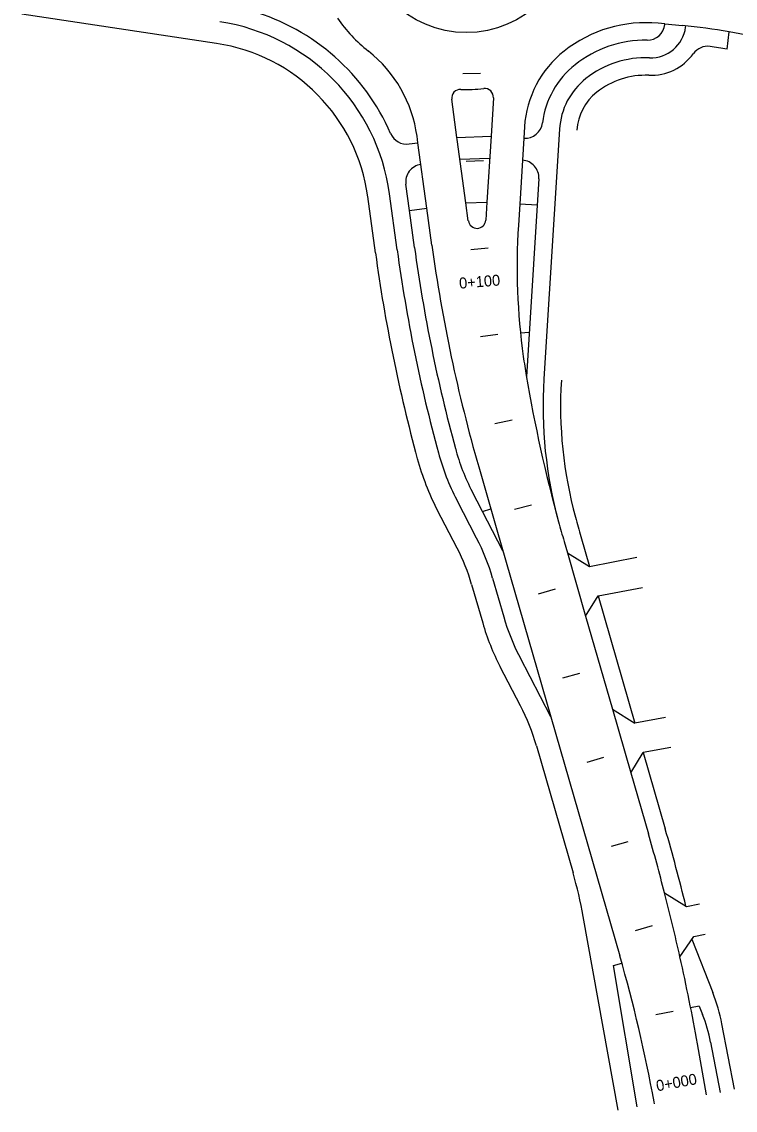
# Model space of a CAD drawing. Extents: x 6503541 to 6503743, y 5888004 to 5888145.
# Drawn here: x 6503692.725 to 6503694.679, y 5888109.241 to 5888112.224 of the extents above; entities that cross this region are included whole.
import ezdxf

# ---------------------------------------------------------------- set-up
doc = ezdxf.new("R2010")
doc.units = 0
doc.layers.add('12', color=7, linetype='Continuous')

msp = doc.modelspace()

# ---------------------------------------------------------------- linework, layer by layer
at = {"layer": '12'}
for p, q in [((6503693.2577, 5888112.1644), (6503692.7245, 5888112.2444)), ((6503694.4861, 5888112.2178), (6503694.4681, 5888112.2196)), ((6503694.4859, 5888112.2166), (6503694.4861, 5888112.2178)), ((6503694.4861, 5888112.2178), (6503694.5342, 5888112.2132)), ((6503694.5428, 5888112.2092), (6503694.5432, 5888112.2124)), ((6503694.6563, 5888112.1489), (6503694.6621, 5888112.196)), ((6503693.9165, 5888111.9068), (6503693.9023, 5888112.0112)), ((6503694.0164, 5888112.0154), (6503694.0098, 5888111.9102)), ((6503694.1016, 5888111.9356), (6503694.0996, 5888111.9046)), ((6503694.1974, 5888111.9296), (6503694.1546, 5888111.2447)), ((6503693.7854, 5888111.8889), (6503693.8095, 5888111.8922)), ((6503693.8095, 5888111.8922), (6503693.8071, 5888111.91)), ((6503693.834, 5888111.7129), (6503693.8095, 5888111.8922)), ((6503693.9165, 5888111.9068), (6503694.0098, 5888111.9102)), ((6503693.9173, 5888111.9008), (6503693.9165, 5888111.9068)), ((6503693.941, 5888111.7275), (6503693.9173, 5888111.9008)), ((6503694.0098, 5888111.9102), (6503693.9985, 5888111.7296)), ((6503694.0996, 5888111.9046), (6503694.0884, 5888111.724)), ((6503694.1001, 5888111.9045), (6503694.0996, 5888111.9046)), ((6503693.9247, 5888111.847), (6503694.0061, 5888111.85)), ((6503694.1408, 5888111.7935), (6503694.1363, 5888111.721)), ((6503693.7864, 5888111.7064), (6503693.7766, 5888111.7784)), ((6503693.6933, 5888111.5903), (6503693.6723, 5888111.7444)), ((6503693.7527, 5888111.5984), (6503693.7317, 5888111.7525)), ((6503693.7864, 5888111.7064), (6503693.834, 5888111.7129)), ((6503693.8003, 5888111.6049), (6503693.7864, 5888111.7064)), ((6503693.8478, 5888111.6114), (6503693.834, 5888111.7129)), ((6503693.941, 5888111.7275), (6503693.9985, 5888111.7296)), ((6503693.9477, 5888111.6783), (6503693.941, 5888111.7275)), ((6503693.9985, 5888111.7296), (6503693.9955, 5888111.6801)), ((6503694.0884, 5888111.724), (6503694.0847, 5888111.6659)), ((6503694.1363, 5888111.721), (6503694.0884, 5888111.724)), ((6503694.1363, 5888111.721), (6503694.1069, 5888111.2508)), ((6503694.1145, 5888111.3725), (6503694.0906, 5888111.37)), ((6503693.9762, 5888111.004), (6503694.026, 5888110.831)), ((6503694.0426, 5888110.7734), (6503693.9584, 5888110.936)), ((6503693.9705, 5888110.8083), (6503693.9158, 5888110.9139)), ((6503693.9172, 5888110.7807), (6503693.8625, 5888110.8863)), ((6503693.9864, 5888110.8818), (6503694.0095, 5888110.8884)), ((6503694.026, 5888110.831), (6503694.1738, 5888110.3186)), ((6503694.2561, 5888110.8128), (6503694.2796, 5888110.7311)), ((6503694.2099, 5888110.7996), (6503694.219, 5888110.7683)), ((6503694.219, 5888110.7683), (6503694.269, 5888110.5946)), ((6503694.219, 5888110.7683), (6503694.2796, 5888110.7311)), ((6503694.2796, 5888110.7311), (6503694.4088, 5888110.756)), ((6503694.0143, 5888110.6984), (6503694.0447, 5888110.593)), ((6503693.9566, 5888110.6818), (6503693.987, 5888110.5764)), ((6503694.303, 5888110.65), (6503694.4247, 5888110.6736)), ((6503694.269, 5888110.5946), (6503694.303, 5888110.65)), ((6503694.303, 5888110.65), (6503694.4034, 5888110.3017)), ((6503694.269, 5888110.5946), (6503694.3425, 5888110.3397)), ((6503694.1738, 5888110.3186), (6503694.0885, 5888110.4832)), ((6503694.0904, 5888110.349), (6503694.0352, 5888110.4556)), ((6503694.3425, 5888110.3397), (6503694.4034, 5888110.3017)), ((6503694.3425, 5888110.3397), (6503694.3928, 5888110.1651)), ((6503694.1738, 5888110.3186), (6503694.3627, 5888109.6633)), ((6503694.4874, 5888110.3171), (6503694.4034, 5888110.3017)), ((6503694.1342, 5888110.2392), (6503694.2345, 5888109.8915)), ((6503694.3928, 5888110.1651), (6503694.4268, 5888110.2206)), ((6503694.5025, 5888110.2344), (6503694.4268, 5888110.2206)), ((6503694.4268, 5888110.2206), (6503694.4871, 5888110.0116)), ((6503694.3928, 5888110.1651), (6503694.4409, 5888109.9983)), ((6503694.4851, 5888109.8361), (6503694.545, 5888109.7991)), ((6503694.545, 5888109.7991), (6503694.5811, 5888109.8061)), ((6503694.3581, 5888109.2405), (6503694.2624, 5888109.7718)), ((6503694.5273, 5888109.6606), (6503694.5651, 5888109.7167)), ((6503694.5598, 5888109.709), (6503694.6174, 5888109.5629)), ((6503694.5651, 5888109.7167), (6503694.5962, 5888109.7232)), ((6503694.3452, 5888109.6369), (6503694.3683, 5888109.6436)), ((6503694.4102, 5888109.2499), (6503694.3452, 5888109.6369)), ((6503694.5803, 5888109.5262), (6503694.5566, 5888109.5215)), ((6503694.5803, 5888109.5262), (6503694.5893, 5888109.5032)), ((6503694.6765, 5888109.2982), (6503694.6423, 5888109.4769)), ((6503694.6005, 5888109.2825), (6503694.5754, 5888109.4224)), ((6503694.6383, 5888109.2893), (6503694.6115, 5888109.4273)), ((6503694.4574, 5888109.2584), (6503694.4565, 5888109.2633))]:
    msp.add_line(p, q, dxfattribs=at)
for points in [[(6503693.9808, 5888112.0823), (6503693.9329, 5888112.0806)], [(6503693.9896, 5888111.8425), (6503693.9416, 5888111.8407)], [(6503693.9545, 5888111.6), (6503694.0024, 5888111.6039)], [(6503694.0284, 5888111.3667), (6503693.9808, 5888111.3601)], [(6503694.0678, 5888111.1314), (6503694.0207, 5888111.1221)], [(6503694.1207, 5888110.8987), (6503694.0742, 5888110.8868)], [(6503694.1853, 5888110.6683), (6503694.1392, 5888110.655)], [(6503694.2518, 5888110.4377), (6503694.2057, 5888110.4244)], [(6503694.3183, 5888110.2071), (6503694.2722, 5888110.1938)], [(6503694.3848, 5888109.9765), (6503694.3387, 5888109.9632)], [(6503694.4513, 5888109.7459), (6503694.4051, 5888109.7326)], [(6503694.5087, 5888109.5107), (6503694.4615, 5888109.5022)]]:
    msp.add_lwpolyline(points, dxfattribs=at)
msp.add_circle((6503693.9421, 5888112.4822), 0.288, dxfattribs=at)
for centre, radius, start, end in [((6503693.1848, 5888111.6778), 0.6, 23.5192, 73.544), ((6503693.1848, 5888111.6778), 0.552, 7.7722, 81.4707), ((6503693.9421, 5888112.4822), 0.432, 215.1701, 231.6188), ((6503694.4337, 5888111.8612), 0.36, 84.5182, 128.3648), ((6503694.4382, 5888112.2212), 0.048, 269.292, 354.5182), ((6503694.3737, 5888110.5409), 1.68, 80.1154, 84.5182), ((6503694.4475, 5888112.2209), 0.096, 267.8024, 352.9756), ((6503694.3737, 5888110.5409), 1.68, 31.9347, 80.1154), ((6503693.1848, 5888111.6778), 0.492, 7.7721, 81.4707), ((6503694.4337, 5888111.8612), 0.312, 89.292, 128.3648), ((6503694.6032, 5888112.1086), 0.048, 81.9971, 144.1931), ((6503694.3827, 5888110.54), 1.632, 80.3497, 81.9971), ((6503693.4504, 5888111.8613), 0.36, 7.7716, 51.6186), ((6503694.389, 5888111.9177), 0.288, 128.3648, 176.4274), ((6503694.4337, 5888111.8612), 0.264, 87.8024, 128.3648), ((6503694.4475, 5888112.2209), 0.144, 267.8024, 324.1931), ((6503694.389, 5888111.9177), 0.24, 128.3648, 173.0615), ((6503694.389, 5888111.9177), 0.192, 128.3648, 176.4274), ((6503694.4337, 5888111.8612), 0.216, 87.8024, 128.3648), ((6503693.9261, 5888112.0145), 0.024, 88.0305, 187.7721), ((6503693.9421, 5888112.4822), 0.444, 268.0305, 276.1691), ((6503693.9924, 5888112.0169), 0.024, 356.4274, 96.1691), ((6503694.389, 5888111.9177), 0.144, 128.3648, 176.4274), ((6503694.1031, 5888111.9524), 0.048, 266.4274, 353.0615), ((6503693.7789, 5888111.9364), 0.048, 203.5192, 277.7721), ((6503693.8242, 5888111.7849), 0.048, 97.7721, 187.7721), ((6503694.0929, 5888111.7965), 0.048, 356.4274, 86.4274), ((6503693.9715, 5888111.6815), 0.024, 187.7721, 356.4274), ((6503695.8812, 5888111.5538), 1.8, 176.4274, 187.9058), ((6503698.0925, 5888112.1907), 4.44, 187.7721, 195.2039), ((6503698.0925, 5888112.1907), 4.38, 187.7721, 195.2039), ((6503698.0925, 5888112.1907), 4.332, 187.7721, 195.2039), ((6503698.0925, 5888112.1907), 4.284, 187.7721, 196.0824), ((6503695.8812, 5888111.5538), 1.8, 187.9058, 189.5941), ((6503698.1649, 5888111.9398), 4.116, 189.594, 195.3072), ((6503695.3523, 5888111.1699), 1.2, 176.4274, 195.3074), ((6503695.3523, 5888111.1699), 1.152, 176.4274, 195.3069), ((6503694.4911, 5888111.212), 0.6, 195.2039, 207.3923), ((6503694.4911, 5888111.212), 0.708, 195.2039, 207.3923), ((6503694.4911, 5888111.212), 0.648, 195.2039, 207.3923), ((6503698.1649, 5888111.9398), 4.116, 195.3075, 196.0824), ((6503698.1649, 5888111.9398), 4.068, 195.3072, 196.0824), ((6503693.4378, 5888110.5322), 0.54, 16.0824, 27.3923), ((6503693.4378, 5888110.5322), 0.6, 16.0824, 27.3923), ((6503694.6212, 5888110.7592), 0.66, 196.0824, 207.3923), ((6503694.6212, 5888110.7592), 0.6, 196.0824, 207.3923), ((6503693.5577, 5888110.073), 0.6, 16.0824, 27.3923), ((6503688.9064, 5888108.4027), 5.808, 13.91969, 16.08236), ((6503688.9064, 5888108.4027), 5.76, 14.41016, 16.08236), ((6503693.0814, 5888109.559), 1.2, 10.2106, 16.0824), ((6503688.9064, 5888108.4027), 5.76, 12.61397, 14.41016), ((6503690.4423, 5888108.5331), 4.08, 10.3108, 16.0824), ((6503688.9064, 5888108.4027), 5.76, 10.1966, 12.61397), ((6503694.1709, 5888109.3869), 0.48, 10.8121, 21.5131), ((6503694.1874, 5888109.3448), 0.432, 11.0076, 21.5131)]:
    msp.add_arc(centre, radius, start, end, dxfattribs=at)

# ---------------------------------------------------------------- texts
for s, rotation, p in [('0+100', 4.6132, (6503693.9236, 5888111.4921)), ('0+000', 10.2085, (6503694.4649, 5888109.2922))]:
    msp.add_text(s, height=0.03, rotation=rotation, dxfattribs=at).set_placement(p)

doc.saveas('drawing.dxf')
